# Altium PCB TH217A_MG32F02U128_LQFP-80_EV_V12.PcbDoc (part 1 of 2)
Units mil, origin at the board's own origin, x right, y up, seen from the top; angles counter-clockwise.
Board outline 4606.3 x 2637.8 mil, 2 copper layers (Top Layer, Bottom Layer); 131 components, 143 nets, 610 pads, 279 vias.
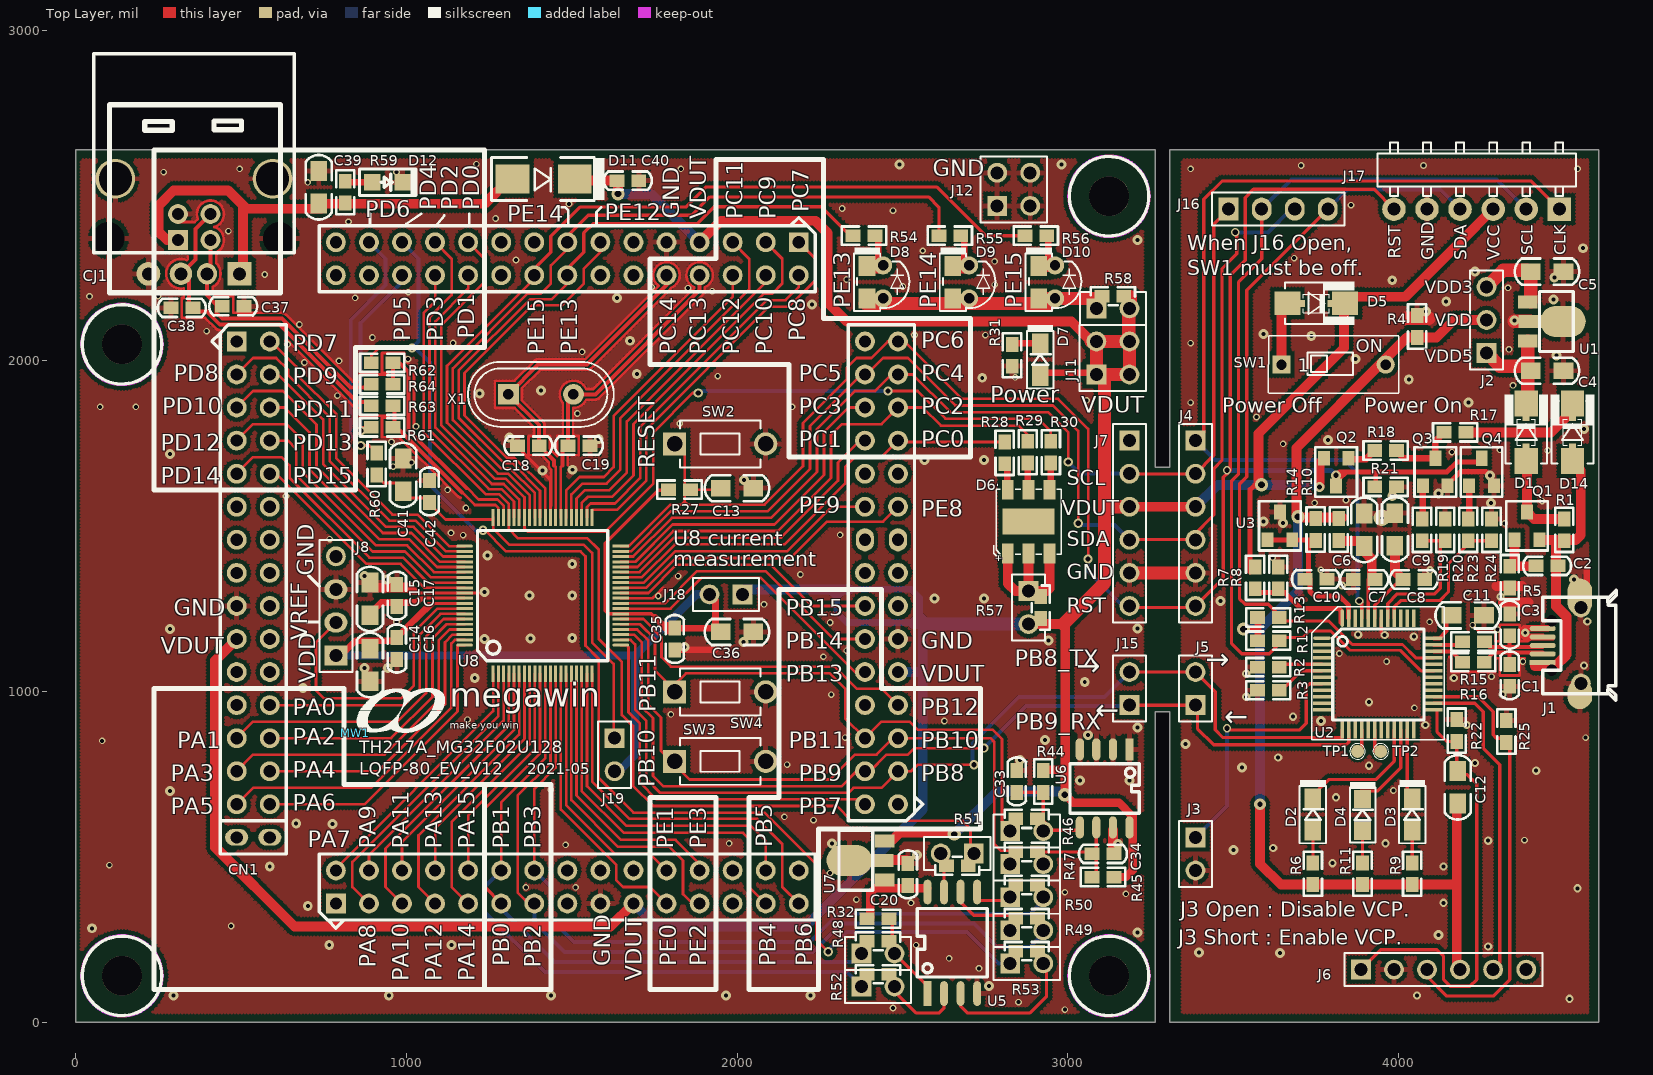
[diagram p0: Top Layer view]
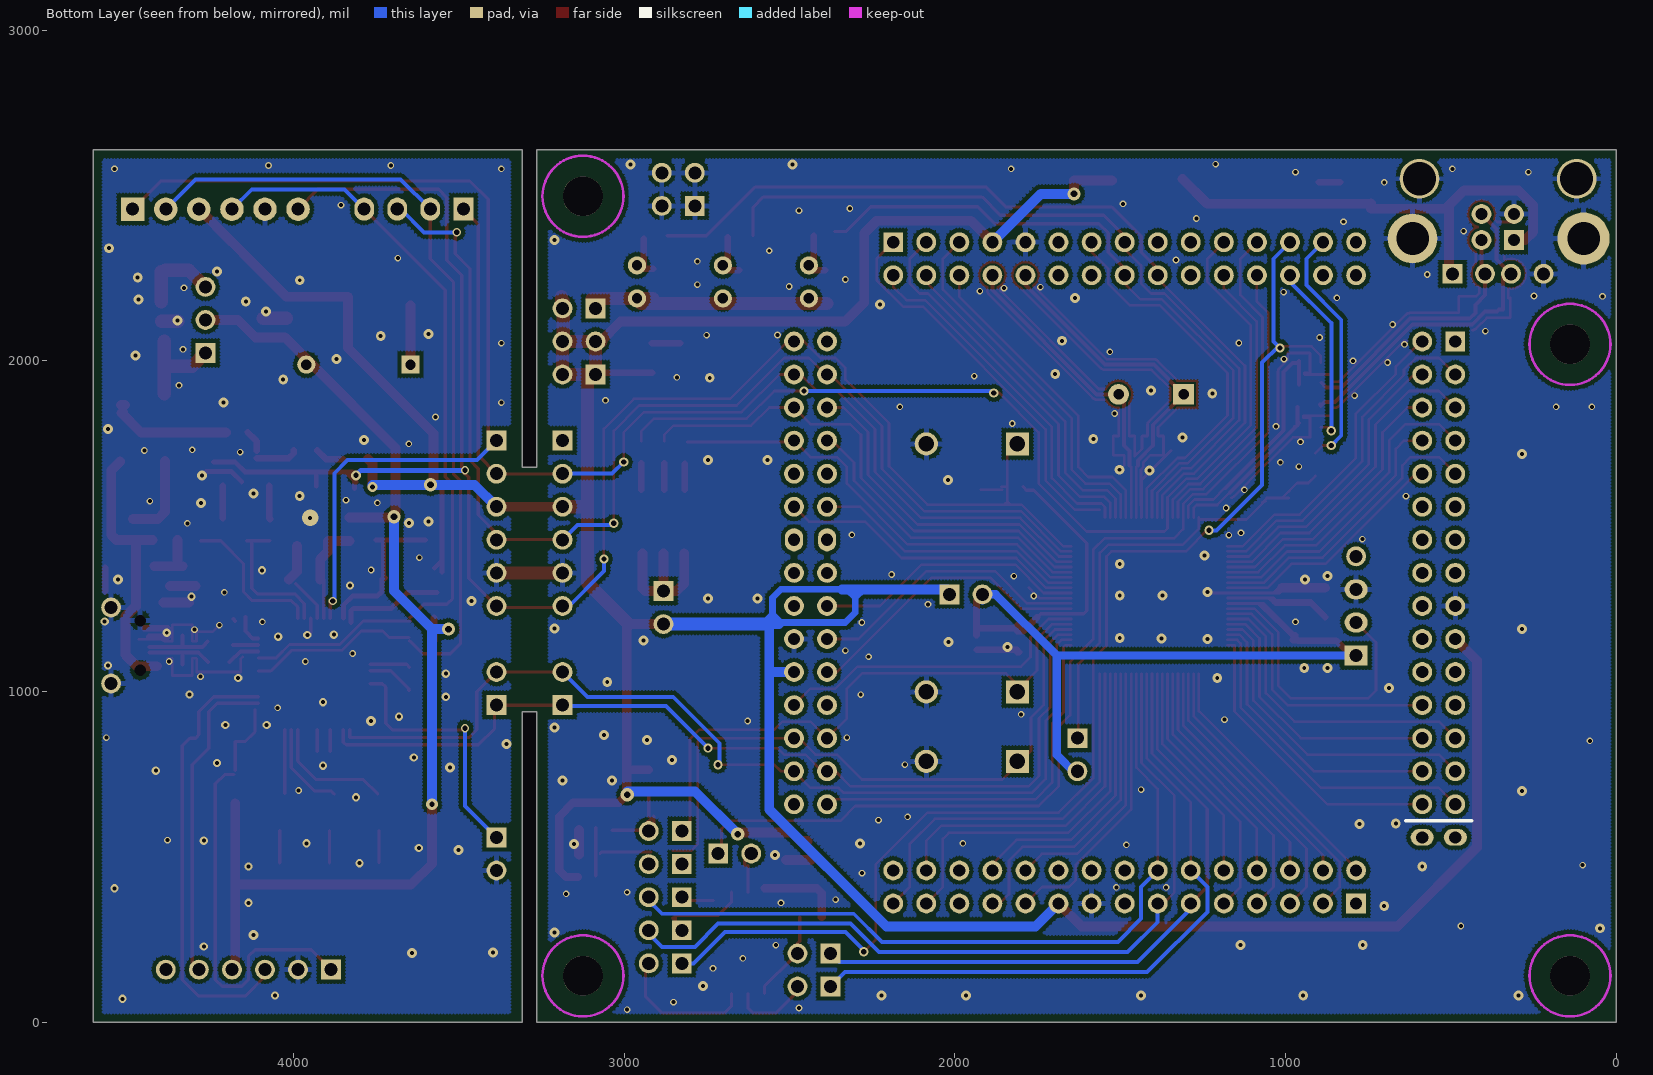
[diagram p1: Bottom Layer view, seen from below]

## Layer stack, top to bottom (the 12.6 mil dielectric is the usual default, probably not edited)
Top Layer: signal copper 1.4
Dielectric: dielectric 12.6, FR-4, Dk 4.8
Bottom Layer: signal copper 1.4

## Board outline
0,0 0,2637.8 3265.2,2637.8 3265.2,1678.74 3308.5,1678.74 3308.5,2637.8 4606.3,2637.8 4606.3,0 3308.5,0 3308.5,938.74 3265.2,938.74 3265.2,0

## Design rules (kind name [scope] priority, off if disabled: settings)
Clearance 12 [All] p1 off: gap=12
Clearance 7 [All] p2 off: gap=7
Clearance 6 [All] p3: gap=6
HoleSize 500-HoleSize [All] p1: absolutevalues=TRUE maxlimit=1500 minlimit=1 maxpercent=80.000 minpercent=20.000
PolygonConnect VIA [ISVIA] p1: connectstyle=Direct reliefconductorwidth=10 reliefentries=4 polygonreliefangle="90 Angle"
PolygonConnect "15 PolygonConnect" [All] p2: connectstyle=Relief reliefconductorwidth=15 reliefentries=4 polygonreliefangle="90 Angle"
RoomDefinition 2_MG32F02U128_V12 [InComponentClass('2_MG32F02U128_V12')] p1: confinementstyle=ConfineIn formatcopy=TRUE lockcomponents=FALSE outline -139,-81 4757,-81 4757,2954 -139,2954
RoomDefinition 1_MLink_V12 [InComponentClass('1_MLink_V12')] p2 off: confinementstyle=ConfineIn formatcopy=TRUE lockcomponents=FALSE outline -50,-126.26 4705.85,-126.26 4705.85,2998 -50,2998
RoutingVias [All] p1: holewidth=16 width=28 viastyle="Through Hole" minholewidth=16 minwidth=25 maxholewidth=28 maxwidth=50
ShortCircuit [All] p1 off: allowed=FALSE
SilkscreenOverComponentPads [All] p1: minsilkscreentomaskgap=10
SolderMaskExpansion [All] p1: expansion=4
UnRoutedNet [All] p1 off:
Width [All] p1: maxlimit=100 minlimit=6 preferedwidth=10
24 further rules are at their usual default settings.

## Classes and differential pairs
component class 2_MG32F02U128_V12: C13 C14 C15 C16 C17 C18 C19 C20 C33 C34 C35 C36 C37 C38 C39 C40 C41 C42 CJ1 CN1 D6 D7 D8 D9 D10 D11 D12 J7 J8 J11 J12 J15 J18 J19 R27 R28 R29 R30 R31 R32 R44 R45 R46 R47 R48 R49 R50 R51 R52 R53 R54 R55 R56 R57 R58 R59 R60 R61 R62 R63 R64 SW2 SW3 SW4 U5 U6 U7 U8 X1
component class 1_MLink_V12: C1 C2 C3 C4 C5 C6 C7 C8 C9 C10 C11 C12 D1 D2 D3 D4 D5 D14 J1 J2 J3 J4 J5 J6 J16 J17 MW1 Q1 Q2 Q3 Q4 R1 R2 R3 R4 R5 R6 R7 R8 R9 R10 R11 R12 R13 R14 R15 R16 R17 R18 R19 R20 R21 R22 R23 R24 R25 SW1 TP1 TP2 U1 U2 U3

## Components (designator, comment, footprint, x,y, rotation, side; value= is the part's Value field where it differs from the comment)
C1 "15pF" 0603C#1 4336.85,1048.74 r90 top
C2 "0.1uF" 0603C#2 4450,1380 r180 top
C3 "15pF" 0603C#1 4336.85,1201.74 r270 top
C4 "4.7uF" 0805C 4450,1970 r0 top
C5 "4.7uF" 0805C 4450,2270 r0 top
C6 "4.7uF" 0805C 3896.81,1488.74 r90 top
C7 "0.1uF" 0603C#2 3896.85,1338.74 r0 top
C8 "0.1uF" 0603C#2 4046.85,1338.74 r180 top
C9 "4.7uF" 0805C 3990,1490 r90 top
C10 "0.1uF" 0603C#2 3750.9,1339.69 r0 top
C11 "4.7uF" 0805C 4210,1230 r0 top
C12 "4.7uF" 0805C 4180,710 r90 top
C13 "4.7uF" 0805C 2000,1615 r180 top
C14 "4.7uF" 0805C 890,1080 r270 top
C15 "4.7uF" 0805C 890,1280 r90 top
C16 "0.1uF" 0603C#1 971.22,1130 r90 top
C17 "0.1uF" 0603C#1 971.22,1290 r270 top
C18 "NC" 0603C#1 1368.85,1743.74 r0 top
C19 "NC" 0603C#1 1521.85,1743.74 r180 top
C20 "1uF" 0603C#1 2516.85,446.74 r270 top
C33 "47pF" 0603C#1 2846.22,727.8 r270 top
C34 "47pF" 0603C#1 3106.85,508.74 r180 top
C35 "0.1uF" 0603C#1 1811.85,1158.74 r90 top
C36 "4.7uF" 0805C 2000,1180 r0 top
C37 "15pF" 0603C#2 476.22,2165 r0 top
C38 "15pF" 0603C#2 321.22,2160 r180 top
C39 "10uF/10V" 0805C 735,2525 r90 top
C40 "1uF" 0603C#2 1670,2545 r0 top
C41 "4.7uF" 0805C 990,1655 r90 top
C42 "0.1uF" 0603C#2 1070,1605 r90 top
CJ1 "CJ-USB-AB" CON_USB-AB 495.35,2263.31 r180 top locked
CN1 "QFP122-CKT" QFP122-P2.54-CKT 1486.85,1358.74 r0 top locked
D1 "1N5817" DIODE_SMA_SOD323 4386.81,1783.74 r90 top
D2 "Yellow" 0805D#1 3741.85,627.95 r90 top
D3 "Green" 0805D#1 4041.85,627.95 r90 top
D4 "Red" 0805D#2 3891.85,626.74 r90 top
D5 "1N5817" DIODE_SMA_SOD323 3751.81,2173.74 r0 top
D6 "GTG5050RGBC" LED6P_RGB_SMD_50X50 2881.85,1513.74 r90 top
D7 "Yellow" 0805D#1 2916.85,2003.74 r90 top
D8 "Red" LED38+0805 2441.85,2238.74 r90 top
D9 "Yellow" LED38+0805 2701.85,2238.74 r90 top
D10 "Green" LED38+0805 2961.85,2238.74 r90 top
D11 "B5817" D5817_SMD_1 1415,2550 r180 top
D12 "LED0805-Green" LED-0805 945,2540 r90 top
D14 "1N5817" DIODE_SMA_SOD323 4526.81,1783.74 r90 top
J1 "Micro USB" JACK_USB_SMD290X220P065 4436.85,1139.21 r180 top locked (schematic designator J8)
J2 "2&3 (0 ohm)" PS3P254 4266.85,2023.74 r90 top
J3 "VCP Option" PS2P254 3386.85,558.74 r270 top
J4 "OnBoard ICP/SWD Connector" PS6P254 3386.85,1758.74 r270 top locked
J5 "NC" PS2P254 3386.85,958.74 r90 top
J6 "CON6" PS6P254 3886.85,158.74 r0 top
J7 "CON6" PS6P254 3186.85,1758.74 r270 top locked
J8 "1&2 (0 ohm)" PS4P254#1 786.85,1108.74 r90 top
J11 "CONN SOCKET 2x2/SM" PS2X2P254 3086.85,1958.74 r0 top
J12 "CONN SOCKET 2x2/SM" PS2X2P254 2786.85,2468.74 r0 top
J15 "NC" PS2P254 3186.85,958.74 r90 top
J16 "When J16 Open, SW1 must be off." PS4P254#2 3486.85,2458.74 r0 top
J17 "Off Board ICP/SWD Connector" PS6P254_90 4486.85,2458.74 r180 top locked
J18 "JUMPER" PS2P254 2016.85,1293.74 r180 top
J19 "JUMPER" PS2P254 1629.85,858.74 r270 top
MW1 "MW-A4" MEGAWIN_3.4 844.85,873.73 r0 top
Q1 "IRLML6402" SOT23 4389.35,1500.71 r0 top
Q2 "2N3906" SOT23 3812.31,1663.74 r180 top
Q3 "3904" SOT23 4111.85,1663.74 r0 top
Q4 "3904" SOT23 4251.85,1663.74 r0 top
R1 "NC" 0603R#1 4501.85,1488.74 r270 top
R2 "0" 0603R#1 3606.85,1073.74 r0 top
R3 "NC" 0603R#1 3606.85,1003.74 r0 top
R4 "3.3K" 0603R#1 4056.85,2103.74 r270 top
R5 "1M" 0603R#1 4336.85,1345.74 r270 top
R6 "1K" 0603R#1 3741.85,448.74 r270 top
R7 "30K" 0603R#1 3566.85,1343.74 r90 top
R8 "10K" 0603R#1 3636.85,1343.74 r270 top
R9 "1K" 0603R#1 4041.85,448.74 r270 top
R10 "10" 0603R#1 3820,1490 r90 top
R11 "1K" 0603R#1 3891.85,448.74 r270 top
R12 "1.5K" 0603R#1 3606.85,1153.74 r180 top
R13 "1.5K" 0603R#1 3606.85,1223.74 r180 top
R14 "1K" 0603R#1 3750,1490 r270 top
R15 "30" 0603R#1 4227.69,1151.05 r180 top
R16 "30" 0603R#1 4226.85,1088.74 r180 top
R17 "4.7K" 0603R#1 4171.81,1783.74 r0 top
R18 "1K" 0603R#1 3961.85,1728.74 r0 top
R19 "4.7K" 0603R#1 4071.85,1488.74 r270 top
R20 "10K" 0603R#1 4141.85,1488.74 r270 top
R21 "1M" 0603R#1 3961.85,1618.74 r180 top
R22 "47K" 0603R#1 4176.85,881.74 r90 top
R23 "4.7K" 0603R#1 4211.85,1488.74 r270 top
R24 "10K" 0603R#1 4281.85,1488.74 r270 top
R25 "47K" 0603R#1 4326.85,878.74 r270 top
R27 "47K" 0603R#1 1826.22,1610.64 r180 top
R28 "510" 0603R#1 2809.41,1721.74 r90 top
R29 "510" 0603R#1 2879.41,1723.74 r90 top
R30 "3K" 0603R#1 2949.41,1723.74 r90 top
R31 "1K" 0603R#1 2831.85,2016.74 r270 top
R32 "47K" 0603R#1 2426.22,312.8 r0 top
R44 "10K" 0603R#1 2926.22,727.8 r90 top
R45 "10K" 0603R#1 3106.85,438.74 r0 top
R46 "NC" PS2p254+0603 2826.22,577.8 r0 top
R47 "NC" PS2p254+0603 2826.22,477.8 r0 top
R48 "NC" PS2p254+0603 2376.22,207.8 r0 top
R49 "NC" PS2p254+0603 2826.22,277.8 r0 top
R50 "NC" PS2p254+0603 2826.22,377.8 r0 top
R51 "NC" PS2p254+0603 2716.22,510 r180 top
R52 "NC" PS2p254+0603 2376.22,107.8 r0 top
R53 "NC" PS2p254+0603 2826.22,177.8 r0 top
R54 "510" 0603R#1 2383.85,2378.74 r180 top
R55 "510" 0603R#1 2643.85,2378.74 r180 top
R56 "510" 0603R#1 2903.85,2378.74 r180 top
R57 "0" PS2p254+0603 2881.85,1303.74 r270 top
R58 "0" PS2p254+0603 3086.85,2158.74 r0 top
R59 "3K" 0603R#2 815,2510 r90 top
R60 "0" 0603R#2 910,1688 r90 top
R61 "0" 0603R#2 926.85,1798.74 r180 top
R62 "0" 0603R#2 926.85,1993.74 r180 top
R63 "0" 0603R#2 926.85,1863.74 r180 top
R64 "0" 0603R#2 926.85,1928.74 r180 top
SW1 "SW KEY-SPST" DIP2_SW 3646.89,1988.74 r0 top
SW2 "SW TACT-SPST" SW_T_2P 1949.06,1748.74 r0 top
SW3 "SW TACT-SPST" SW_T_2P 1949.06,788.74 r0 top
SW4 "SW TACT-SPST" SW_T_2P 1949.06,998.74 r0 top
TP1 "T POINT A" PIN1_1H0 3876.85,818.74 r270 top
TP2 "T POINT A" PIN1_1H0 3946.85,818.74 r270 top
U1 "AIC1734-33(SOT-89)" SOT89 4391.81,2119.06 r270 top
U2 "MG84FG516_LQFP48" LQFP48_7X7_050 3938.32,1053.13 r270 top locked
U3 "TL431A" SOT23 3641.81,1500.71 r0 top
U5 "MX25LXX-SOP" SO8_208P127 2651.22,240 r0 top
U6 "24C16-SOP" SO8_150P127 3186.85,824.96 r270 top
U7 "AIC1734-33(SOT-89)" SOT89 2446.22,489.06 r90 top
U8 "MG32F02U128_LQFP80" QFP80-P0.4-Z12X12 1412.24,1289.96 r0 top locked
X1 "NC" X49U 1406.85,1898.74 r0 top

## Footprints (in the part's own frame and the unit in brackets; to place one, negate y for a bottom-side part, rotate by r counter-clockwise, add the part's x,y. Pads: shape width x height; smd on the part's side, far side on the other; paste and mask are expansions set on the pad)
0603C#1 [mil]
  rect 45x38 smd: 1(33,0) 2(-33,0)
  silkscreen extent -72,-28 72,28
0603C#2 [mil]
  rect 45x38 smd: 1(-33,0) 2(33,0)
  silkscreen extent -72,-28 72,28
0603R#1 [mil]
  rect 45x38 smd: 1(33,0) 2(-33,0)
  silkscreen extent -67,-28 67,28
0603R#2 [mil]
  rect 45x38 smd: 1(-33,0) 2(33,0)
  silkscreen extent -67,-28 67,28
0805C [mil]
  rect 60x50 smd: 1(-49.21,0) 2(49.21,0)
  silkscreen extent -97,-39 97,39
0805D#1 [mil]
  rect 60x50 smd: 1(-49.21,0) 2(49.21,0)
  silkscreen extent -87,-40 105,40
0805D#2 [mil]
  rect 55.12x51.18 smd: 1(-48,0) 2(48,0)
  silkscreen extent -84,-39 100,38
CON_USB-AB [mm]
  rect 1.824x1.824 / inner round 1.524 / far side rect 1.524x1.524 hole 1: 1(0,0)
  oval 1.524x1.651 / inner round 1.524 / far side round 1.524 hole 1: 2(2.5,0)
  round 1.724 / inner round 1.524 / far side round 1.524 hole 1: 3(4.5,0)
  round 1.824 / inner round 1.524 / far side round 1.524 hole 1: 4(7,0)
  round 1.524 / inner round 1.524 / far side round 3.81 hole 2.5: 5(-3.07,-2.71)
  round 1.524 / inner round 1.524 / far side round 4.013 hole 2.5: 6(10.07,-2.71)
  rect 1.524x1.524 hole 0.94: 7(4.73,-2.59)
  round 1.524 hole 0.94: 8(2.23,-2.59) 9(2.23,-4.59) 10(4.73,-4.59)
  round 3.048 hole 2.54: 11(-2.54,-7.3) 12(9.54,-7.3)
  silkscreen extent -4.2,-16.91 11.2,1.46
D5817_SMD_1 [mm]
  rect 2.6x2.2 smd: 1(2.39,0) 2(-2.39,0)
  silkscreen extent -4.67,-1.65 4,1.65
DIODE_SMA_SOD323 [mm]
  rect 2x1.8 smd: 1(-2.2,0) 2(2.2,0)
  rect 0.95x0.54 smd: 1(-1.35,0) 2(1.35,0)
  silkscreen extent -2.4,-1.68 2.92,1.68
DIP2_SW [mm]
  rect 1.4x1.4 hole 0.8: 1(0,0)
  round 1.4 hole 0.8: 2(8,0)
  silkscreen extent -1.02,-2.2 9.02,2.2
JACK_USB_SMD290X220P065 [mm]
  rect 1.9x1.8 on Mech2: 0(-2.85,-1.15) 0(-2.85,1.15)
  round 0.8 hole 0.9 unplated: 1(-0.7,1.9) 5(-0.7,-1.9)
  rect 2x0.4 smd: 1(0,1.3)
  oval 2x0.4 smd: 2(0,0.65) 3(0,0) 4(0,-0.65) 5(0,-1.3)
  round 1.524 hole 1: 5(-2.931,2.921) 6(-2.931,-2.921)
  oval 1.9x2.3 smd: 5(-2.85,3.75)
  oval 1.9x2.794 smd: 6(-2.85,-3.75)
  silkscreen extent -5.65,-4.25 -0.01,4.2
LED6P_RGB_SMD_50X50 [mm]
  rect 2x4 smd: 0(0,0)
  rect 1.5x0.9 smd: 1(-2.45,1.6) 2(2.45,1.6) 3(-2.45,0) 4(2.45,0) 5(-2.45,-1.6) 6(2.45,-1.6)
  silkscreen extent -2.63,-2.5 2.5,2.69
LED38+0805 [mm]
  round 1.4 hole 0.8: 1(-1.27,0) 2(1.27,0)
  rect 1.524x1.27 smd: 1(-1.267,1.237) 2(1.233,1.237)
  silkscreen extent -2.23,-2.02 2.64,2.25
LED-0805 [mil]
  rect 50x50 smd: 1(0,48) 2(0,-44)
  silkscreen extent -40,-83 40,87
LQFP48_7X7_050 [mm]
  oval 0.254x1.35 smd: 1(-2.75,-4.292)
  rect 0.254x1.35 smd: 2(-2.25,-4.292) 3(-1.75,-4.292) 4(-1.25,-4.292) 5(-0.75,-4.292) 6(-0.25,-4.292) 7(0.25,-4.292) 8(0.75,-4.292) 9(1.25,-4.292) 10(1.75,-4.292) 11(2.25,-4.292) 12(2.75,-4.292) 25(2.763,4.292) 26(2.263,4.292) 27(1.763,4.292) 28(1.263,4.292) 29(0.763,4.292) 30(0.263,4.292) 31(-0.237,4.292) 32(-0.737,4.292) 33(-1.237,4.292) 34(-1.737,4.292) 35(-2.237,4.292) 36(-2.737,4.292)
  rect 1.35x0.254 smd: 13(4.286,-2.744) 14(4.286,-2.244) 15(4.286,-1.744) 16(4.286,-1.244) 17(4.286,-0.744) 18(4.286,-0.244) 19(4.286,0.256) 20(4.286,0.756) 21(4.286,1.256) 22(4.286,1.756) 23(4.286,2.256) 24(4.286,2.756) 37(-4.286,2.756) 38(-4.286,2.256) 39(-4.286,1.756) 40(-4.286,1.256) 41(-4.286,0.756) 42(-4.286,0.256) 43(-4.286,-0.244) 44(-4.286,-0.744) 45(-4.286,-1.244) 46(-4.286,-1.744) 47(-4.286,-2.244)
  oval 1.35x0.254 smd: 48(-4.286,-2.744)
  silkscreen extent -5.15,-5.09 5.05,5.11
MEGAWIN_3.4 [mil]
  silkscreen extent 5,3 272,136
PIN1_1H0 [mm]
  round 1 smd: 1(0,0)
  silkscreen extent -0.6,-0.6 0.6,0.6
PS2P254 [mil]
  rect 60x60 hole 39.37: 1(0,0)
  round 60 hole 39.37: 2(100,0)
  silkscreen extent -50,-50 150,50
PS2p254+0603 [mil]
  rect 60x60 hole 39.37: 1(0,0)
  rect 45x38 smd: 1(17,36.85) 2(83,36.85)
  round 60 hole 39.37: 2(100,0)
  silkscreen extent -50,-50 150,64
PS2X2P254 [mil]
  rect 60x60 hole 39.37: 1(0,0)
  round 60 hole 39.37: 2(0,100) 3(100,0) 4(100,100)
  silkscreen extent -50,-50 150,150
PS3P254 [mil]
  rect 60x60 hole 39.37: 1(0,0)
  round 60 hole 39.37: 2(100,0) 3(200,0)
  silkscreen extent -50,-50 250,50
PS4P254#1 [mil]
  rect 60x70 hole 39.37: 1(0,0)
  oval 60x70 hole 39.37: 2(100,0) 3(200,0)
  round 60 hole 39.37: 4(300,0)
  silkscreen extent -50,-50 350,50
PS4P254#2 [mil]
  rect 60x70 hole 39.37: 1(0,0)
  oval 60x70 hole 39.37: 2(100,0) 3(200,0) 4(300,0)
  silkscreen extent -50,-50 350,50
PS6P254 [mil]
  rect 60x60 hole 39.37: 1(0,0)
  round 60 hole 39.37: 2(100,0) 3(200,0) 4(300,0) 5(400,0) 6(500,0)
  silkscreen extent -50,-50 550,50
PS6P254_90 [mm]
  rect 1.8x1.8 hole 1: 1(0,0)
  round 1.8 hole 1: 2(2.54,0) 3(5.08,0) 4(7.62,0) 5(10.16,0) 6(12.7,0)
  silkscreen extent -1.27,-5.11 13.97,-1
QFP80-P0.4-Z12X12 [mm]
  rect 0.229x1.27 smd: 1(-3.8,-6) 2(-3.4,-6) 3(-3,-6) 4(-2.6,-6) 5(-2.2,-6) 6(-1.8,-6) 7(-1.4,-6) 8(-1,-6) 9(-0.6,-6) 10(-0.2,-6) 11(0.2,-6) 12(0.6,-6) 13(1,-6) 14(1.4,-6) 15(1.8,-6) 16(2.2,-6) 17(2.6,-6) 18(3,-6) 19(3.4,-6) 20(3.8,-6) 41(3.8,6) 42(3.4,6) 43(3,6) 44(2.6,6) 45(2.2,6) 46(1.8,6) 47(1.4,6) 48(1,6) 49(0.6,6) 50(0.2,6) 51(-0.2,6) 52(-0.6,6) 53(-1,6) 54(-1.4,6) 55(-1.8,6) 56(-2.2,6) 57(-2.6,6) 58(-3,6) 59(-3.4,6) 60(-3.8,6)
  oval 1.27x0.229 smd: 21(6,-3.8) 61(-6,3.8) 80(-6,-3.8)
  rect 1.27x0.229 smd: 22(6,-3.4) 23(6,-3) 24(6,-2.6) 25(6,-2.2) 26(6,-1.8) 27(6,-1.4) 28(6,-1) 29(6,-0.6) 30(6,-0.2) 31(6,0.2) 32(6,0.6) 33(6,1) 34(6,1.4) 35(6,1.8) 36(6,2.2) 37(6,2.6) 38(6,3) 39(6,3.4) 40(6,3.8) 62(-6,3.4) 63(-6,3) 64(-6,2.6) 65(-6,2.2) 66(-6,1.8) 67(-6,1.4) 68(-6,1) 69(-6,0.6) 70(-6,0.2) 71(-6,-0.2) 72(-6,-0.6) 73(-6,-1) 74(-6,-1.4) 75(-6,-1.8) 76(-6,-2.2) 77(-6,-2.6) 78(-6,-3) 79(-6,-3.4)
  silkscreen extent -5,-5 5,5
QFP122-P2.54-CKT [mil]
  rect 60x60 hole 37: 1(-700,-1000) 61(700,1000) 91(-1000,700)
  round 60 hole 37: 2(-700,-900) 3(-600,-1000) 4(-600,-900) 5(-500,-1000) 6(-500,-900) 7(-400,-1000) 8(-400,-900) 9(-300,-1000) 10(-300,-900) 11(-200,-1000) 12(-200,-900) 13(-100,-1000) 14(-100,-900) 15(0,-1000) 16(0,-900) 17(100,-1000) 18(100,-900) 19(200,-1000) 20(200,-900) 21(300,-1000) 22(300,-900) 23(400,-1000) 24(400,-900) 25(500,-1000) 26(500,-900) 27(600,-1000) 28(600,-900) 29(700,-1000) 30(700,-900) 31(1000,-700) 32(900,-700) 33(1000,-600) 34(900,-600) 35(1000,-500) 36(900,-500) 37(1000,-400) 38(900,-400) 39(1000,-300) 40(900,-300) 41(1000,-200) 42(900,-200) 43(1000,-100) 44(900,-100) 45(1000,0) 46(900,0) 49(1000,200) 50(900,200) 51(1000,300) 52(900,300) 53(1000,400) 54(900,400) 55(1000,500) 56(900,500) 57(1000,600) 58(900,600) 59(1000,700) 60(900,700) 62(700,900) 63(600,1000) 64(600,900) 65(500,1000) 66(500,900) 67(400,1000) 68(400,900) 69(300,1000) 70(300,900) 71(200,1000) 72(200,900) 73(100,1000) 74(100,900) 75(0,1000) 76(0,900) 77(-100,1000) 78(-100,900) 79(-200,1000) 80(-200,900) 81(-300,1000) 82(-300,900) 83(-400,1000) 84(-400,900) 85(-500,1000) 86(-500,900) 87(-600,1000) 88(-600,900) 89(-700,1000) 90(-700,900) 92(-900,700) 93(-1000,600) 94(-900,600) 95(-1000,500) 96(-900,500) 97(-1000,400) 98(-900,400) 99(-1000,300) 100(-900,300) 101(-1000,200) 102(-900,200) 103(-1000,100) 104(-900,100) 105(-1000,0) 106(-900,0) 107(-1000,-100) 108(-900,-100) 109(-1000,-200) 110(-900,-200) 111(-1000,-300) 112(-900,-300) 113(-1000,-400) 114(-900,-400) 115(-1000,-500) 116(-900,-500) 117(-1000,-600) 118(-900,-600) 119(-1000,-700) 120(-900,-700)
  oval 55x70 hole 37: 47(1000,100) 48(900,100)
  oval 70x50 hole 37: 121(-1000,-800) 122(-900,-800)
  silkscreen extent -1075,-1075 1075,1075
SO8_150P127 [mil]
  rect 67x25 smd: 1(0,0)
  oval 67x25 smd: 2(0,-50) 3(0,-100) 4(0,-150) 5(236.22,-150) 6(236.22,-100) 7(236.22,-50) 8(236.22,0)
  silkscreen extent 43,-180 193,30
SO8_208P127 [mm]
  rect 0.6x1.9 smd: 1(-1.905,-3.9)
  oval 0.6x1.9 smd: 2(-0.635,-3.9) 3(0.635,-3.9) 4(1.905,-3.9) 5(1.905,3.9) 6(0.635,3.9) 7(-0.635,3.9) 8(-1.905,3.9)
  silkscreen extent -2.69,-2.63 2.69,2.63
SOT23 [mil]
  rect 36x43.31 smd: 1(-37.5,-41.97) 2(37.5,-41.97)
  rect 36x46.06 smd: 3(0.5,41.97)
  silkscreen extent -63,-74 63,75
SOT89 [mm]
  rect 1.016x1.5 smd: 1(-1.5,0) 3(1.5,0)
  oval 2.4x3.5 smd: 2(0,2.7)
  rect 1.016x2.6 smd: 2(0,0.6)
  silkscreen extent -2.3,0.9 2.3,3.5
SW_T_2P [mil]
  rect 70x70 hole 47.24: 1(-137.79,0)
  round 70 hole 47.24: 2(137.8,0)
  silkscreen extent -122,-71 122,71
X49U [mm]
  rect 1.6x1.6 hole 0.8: 1(-2.5,0)
  round 1.6 hole 0.8: 2(2.5,0)
  silkscreen extent -5.6,-2.5 5.6,2.5

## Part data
C1 C3 C7 C12 C13 C14 C15 C16 C17 C35 C36 C42: library part "CAP NP_Dup1"
C2 C8 C10: library part "CAP NP"
C4 C5: library part "C NP"
C6 C9 C11 C41: library part CAP
C18 C19: library part "C NP_Dup1"
C20 C33 C34 C37 C38 C40: library part CAP-NP
C39: library part CAP-POL
CN1: "CN1"
D1 D5 D14: library part "DIODE SCHOTTKY"
D2 D3 D4: library part Led0_0
D6: library part LED_GTG5050RGBC
D7 D8 D9 D10: library part LED_Dup1
D11: library part DIODE-SCHOTTKY-2
D12: library part LED
J1 J7: library part CON6_Dup1
J2: library part CON3
J3 J5 J15: library part CON2
J4 J17: library part CON6
J8 J16: library part CON4
MW1: library part MW_A4_2
Q1: library part "MOSFET P GSD"
Q2: library part "PNP BEC"
Q3 Q4: library part "NPN BEC"
R1 R2 R3 R4 R27: library part R_Dup4
R5 R6 R7 R8 R9 R11 R12 R13 R17 R18 R19 R22 R23 R25: library part R_Dup2
R10 R14 R15 R16 R28 R29 R30 R31 R32 R46 R47 R48 R49 R50 R51 R52 R53 R54 R55 R56 R57 R58 R60 R61 R62 R63 R64: library part R_Dup5
R20 R21 R24: library part R_Dup1
R44 R45 R59: library part R
U1 U7: library part AIC1722-33
U3: library part TL431/CYL
U5: library part ICM-25LXX
U6: library part ICM-24CXX
U8: library part IC-MG32F02U128-LQFP80
X1: library part CRYSTAL

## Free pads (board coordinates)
  round 120 hole 120 unplated: 0(140,140) 0(140,2050) 0(3125.2,140) 0(3125.2,2497.8)

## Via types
v1: diameter 20, hole 12, Top Layer to Bottom Layer, tented both sides, 126 vias
v2: diameter 30, hole 12, Top Layer to Bottom Layer, tented both sides, 95 vias
v3: diameter 25, hole 12, Top Layer to Bottom Layer, tented both sides, 32 vias
v4: diameter 28, hole 16, Top Layer to Bottom Layer, tented both sides, 12 vias
v5: diameter 40, hole 20, Top Layer to Bottom Layer, tented both sides, 6 vias
v6: diameter 25, hole 16, Top Layer to Bottom Layer, tented both sides, 4 vias
v7: diameter 30, hole 16, Top Layer to Bottom Layer, tented both sides, 2 vias
v8: diameter 50, hole 12, Top Layer to Bottom Layer, tented both sides, 1 vias
v9: diameter 35, hole 16, Top Layer to Bottom Layer, tented both sides, 1 vias

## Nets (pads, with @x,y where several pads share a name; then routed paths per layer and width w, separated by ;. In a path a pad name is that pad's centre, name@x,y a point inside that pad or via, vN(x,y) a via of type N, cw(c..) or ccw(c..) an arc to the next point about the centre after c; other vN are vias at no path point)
2.495V: C10.1 R14.1 U2.47 U3.1 U3.2 | length 482.7
  Top Layer w15: U3.1@3601.81,1458.74 U3.1@3604.31,1458.74 U3.2@3679.31,1458.74 ; U3.2@3689.31,1458.74 3750,1458.74 R14.1@3751.81,1458.74 ; C10.1@3722.16,1343.94 C10.1@3733.07,1333.03 ; C10.1@3728.07,1339.69 3728.07,1456.77 ; C10.1@3733.07,1339.69 C10.1@3733.07,1333.03 ; U2.47@3849.99,1221.87 3849.99,1260.6 3821.85,1288.74 3746.85,1288.74 3733.07,1302.52 C10.1@3733.07,1333.03
+5V_USB: C39.1 CJ1.1 CJ1.7 D11.1 R59.1 | length 1499
  Top Layer w30: CJ1.7@319.13,2365.28 CJ1.7@309.13,2365.28 275.94,2365.28 251.22,2390 251.22,2470 296.22,2515 461.22,2515 505.35,2470.87 ; CJ1.1@505.35,2263.31 505.35,2470.87 ; C39.1@741.85,2460 735,2460 516.22,2460 505.35,2470.87 ; C39.1@741.85,2475.32 742.17,2475 815,2475 1236.85,2475 D11.1@1311.85,2550
CHIP_VDD: C14.1 C16.1 C35.1 C36.1 J8.1 J18.2 J19.2 R27.1 U8.27 U8.72 | length 3106.5
  Top Layer w8: 1054.25,1253.74 1066.85,1266.34
  Top Layer w9: 1061.85,1243.74 1084.45,1266.34 ; 1066.85,1266.34 1084.45,1266.34 ; U8.72@1176.02,1266.34 1084.45,1266.34
  Top Layer w10: 1751.85,1223.74 1740.75,1234.84 U8.27@1648.46,1234.84 1610.75,1234.84 1601.85,1243.74 1601.85,1448.74 1761.85,1608.74 1783.85,1608.74 1789.49,1614.38 R27.1@1793.85,1618.74
  Top Layer w20: J8.1@796.85,1103.74 846.85,1153.74 890,1153.74 961.85,1153.74 971.17,1163.06 C16.1@978.11,1170 ; C16.1@971.22,1155 977.54,1155 C16.1@978.38,1155.84 ; C16.1@971.22,1170 C16.1@978.11,1170 ; 1066.85,1258.74 C16.1@978.11,1170 ; 1751.85,1223.74 1793.85,1181.74 C35.1@1811.85,1181.74 ; 1776.22,1200 C35.1@1811.85,1200 ; C35.1@1811.85,1191.74 C36.1@1935,1191.74 ; J18.2@1916.85,1293.74 1935,1275.59 C36.1@1935,1191.74 ; C36.1@1935,1170 1935,1180 C36.1@1935,1191.74
  Bottom Layer w25: J8.1@786.85,1108.74 1692,1108.74 ; J19.2@1633,749 1636.3,752.3 1692,808 1692,1108.74 ; J18.2@1916.85,1293.74 1877,1293.74 1692,1108.74
  Bottom Layer w30: J18.2@1916.85,1278.74 J18.2@1916.85,1293.74
D+: C3.1 J1.3 R15.2 | length 211.2
  Top Layer w12: R15.2@4260.69,1151.05 4276.52,1135.21 J1.3@4436.85,1135.21 ; 4336.85,1140.21 C3.1@4336.85,1168.74
D-: C1.1 J1.2 R16.2 | length 219.3
  Top Layer w12: R16.2@4259.85,1088.74 4288.32,1117.21 J1.2@4436.85,1117.21 ; C1.1@4336.85,1081.74 4336.85,1112.21
DET_VDUT: R7.2 R8.1 U2.48 | length 317.8
  Top Layer w15: R7.2@3566.85,1298.74 3636.85,1298.74 3656.85,1298.74 3704.09,1251.51 3819.09,1251.51 3826.85,1243.74 3826.85,1221.87 U2.48@3826.85,1208.74
DUT_CLK: J4.1 J17.1 U2.45 | length 2898.3
  Top Layer w10: J4.1@3386.85,1758.74 3411.85,1783.74 3411.85,2488.74 3466.85,2543.74 4401.85,2543.74 J17.1@4486.85,2458.74 ; v6@3876.73,1273.74 3879.23,1271.24 3889.36,1261.11 ; U2.45@3889.36,1221.87 3889.36,1261.11 ; v6@3889.36,1273.74 3889.36,1261.11
  Bottom Layer w12: J4.1@3386.85,1758.74 3445.59,1700 3836.73,1700 3876.73,1660 3876.73,1568.74 ; v6@3876.73,1273.74 3876.73,1568.74 ; 3876.73,1606.93 3876.73,1568.74
  other v6: 3881.73,1273.74
FAIL: D4.2 U2.22 | length 278.6
  Top Layer w10: D4.2@3876.85,689.74 3885.85,698.74 3891.85,698.74 3936.85,698.74 4007.47,769.36 U2.22@4007.47,884.39
FLASH_CEN: R32.1 R48.2 U5.1 | length 275.7
  Top Layer w10: R32.1@2469.22,317.8 2469.22,312.8 2469.22,244.8 2491.22,222.8 2491.22,207.8 2491.22,192.8 2576.22,107.8 U5.1@2576.22,86.46
FLASH_D0: R50.1 U5.5 | length 94.3
  Top Layer w10: U5.5@2731.22,367.8 R50.1@2825.47,367.8
FLASH_D1: R52.2 U5.2 | length 261.8
  Top Layer w10: R52.2@2476.22,127.8 R52.2@2476.22,107.8 2476.22,92.8 2541.22,27.8 2611.22,27.8 2626.22,42.8 U5.2@2626.22,86.46
FLASH_D2: R53.2 U5.3 | length 427.7
  Top Layer w10: U5.3@2676.22,86.46 2676.22,47.8 2696.22,27.8 2886.22,27.8 2936.22,77.8 R53.2@2936.22,177.8
FLASH_D3: R51.2 U5.7 | length 132.7
  Top Layer w10: R51.2@2621.22,520 2623.72,517.5 2636.22,505 R51.2@2636.22,473.15 ; U5.7@2626.22,393.19 U5.7@2626.22,393.54 R51.2@2626.22,472.8
FLASH_SCK: R49.1 U5.6 | length 241.4
  Top Layer w10: U5.6@2676.22,393.54 2676.22,362.8 2716.22,322.8 2843.22,322.8 2845.07,322.8 2846.37,321.5 2846.37,314.65 2846.37,307.8 2848.22,309.65 R49.1@2853.22,314.65
GND_POWER: C1.2 C3.2 C4.2 C5.2 C6.2 C7.1 C8.1 C9.2 C10.2 C11.2 C13.1 C14.2 C15.2 C16.2 C17.2 C18.2 C19.2 C20.2 C33.2 C34.2 C35.2 C36.2 C37.2 C38.2 C39.2 C40.2 C41.2 C42.2 CJ1.4 CJ1.5 CJ1.6 CJ1.10 CJ1.11 CJ1.12 CN1.17 CN1.41 CN1.69 CN1.107 D12.2 J1.4 J1.5 J1.6 J3.2 J4.5 J6.2 J7.5 J8.3 J12.1 J12.2 J12.3 J12.4 J17.5 Q3.2 Q4.2 R2.2 R3.2 R4.2 R5.1 R8.2 R20.2 R21.2 R22.1 R24.2 R25.2 R31.1 SW2.2 SW3.2 SW4.2 U1.2 U2.42 U3.3 U5.4 U6.1 U6.2 U6.3 U6.4 U6.7 U7.2 U8.30 U8.49 U8.70 | length 9632.2
  Top Layer w8: CJ1.10@310,2420 359.5,2420 369.16,2429.65 cw(c407.56,2444.02) 448.56,2444.02 cw(c407.56,2444.02) 419,2404.65 cw(c407.56,2365.28) 448.56,2365.28 cw(c407.56,2365.28) 424.56,2327.97 424.56,2296.1 cw(c396.93,2265.81) 437.93,2265.81 437.93,2260.81 cw(c396.93,2260.81) 413.93,2223.5 413.93,2205.7 424.63,2195 476.72,2195 476.72,2145 509.22,2145 623.68,2145 ; 338.85,2316.5 338.85,2308.01 335.58,2304.74 ccw(c318.19,2263.31) 326.19,2219.09 326.19,2190 320.72,2190 320.72,2130 391.55,2130 423.55,2098 ; 633.84,2059.86 640.4,2059.86 642.32,2059.86 646.34,2055.84 699.2,2002.98 799.2,1902.98 839.18,1863 ; 635.7,2140.02 ccw(c623.68,2128) 623.68,2145 ; 926.35,1833.74 860.35,1833.74 860.35,1858 851.22,1858 ; 926.35,1958.74 860.35,1958.74 860.35,1937 838.72,1937 670.97,2104.75 635.72,2140 ccw(c623.68,2128) 623.68,2145 ; 927.35,1833.74 947.22,1833.74 947.22,1828.74 926.35,1828.74 926.35,1768.74 955,1768.74 977.98,1768.74 1016.26,1730.47 1089.36,1657.36 1130.86,1615.86 1156.47,1590.25 ccw(c1168.49,1602.27) 1164.18,1585.83 ; 927.35,1958.74 942.85,1958.74 942.85,1963.74 926.35,1963.74 926.35,2023.74 993.35,2023.74 993.35,2005 993.35,2003.21 998.28,1998.28 1018.22,1978.34 cw(c1006.22,1966.3) 1023.22,1966.3 ; 1018.24,1978.32 cw(c1006.22,1966.3) 1023.22,1966.3 ; v1@1023.22,1797.04 1023.22,1802 1023.22,1966.3 ; U8.49@1437.11,1526.18 1437.11,1561.18 ; 1437.61,1561.18 1437.61,1670.51 cw(c1446.61,1683.74) 1430.61,1683.74 1430.61,1692.35 1408.22,1714.74 1369.35,1714.74 1369.35,1772.74 1385.85,1772.74 1385.85,1798.69 1327.29,1857.24 1266.93,1857.24 1266.93,1940.24 1327.29,1940.24 1387.1,2000.04 ; 1456.36,1711.86 1434.35,1733.87 1434.35,1772.74 1417.85,1772.74 1417.85,1805.32 ; 1456.35,1714.74 1456.35,1772.74 1472.85,1772.74 1472.85,1872.85 cw(c1505.28,1898.74) 1543.56,1914.74 1565.22,1914.74 1861.12,2210.63 1870.85,2220.37 ; 1488.36,1683.74 1488.36,1714.74 1521.35,1714.74 1521.35,1772.74 1504.85,1772.74 1504.85,1840.64 1504.85,1857.25 ccw(c1505.28,1898.74) 1543.56,1882.74 1571.85,1882.74 ; 1558.16,1977.43 cw(c1546.85,1988.74) 1546.85,1972.74 ; 1583.16,1887.43 cw(c1571.85,1898.74) 1571.85,1882.74 ; U8.30@1648.46,1282.09 1745.2,1282.09 1756.85,1293.74 1776.85,1313.74 ; 1798.16,2217.43 ccw(c1786.85,2228.74) 1801.04,2221.34 ; 1870.85,2222.08 cw(c1886.85,2258.74) 1926.85,2258.74 cw(c1886.85,2258.74) 1902.85,2222.08 1902.85,2213.74 ; 1898.16,2202.43 ccw(c1886.85,2213.74) 1902.85,2213.74 ; 4154.02,1104.53 4160.35,1098.2 4160.35,1058.74 4226.35,1058.74 ; v1(4225,1200.64) 4244.6,1181.05 4294.19,1181.05 4294.19,1152.21 4306.85,1152.21 4306.85,1187.05 4306.85,1202.24 4366.85,1202.24 4366.85,1152.21 4391.67,1152.21 cw(c4405.35,1139.21) 4405.35,1158.09 4436.85,1158.09 J1.4@4468.35,1158.09 ; 4227.35,1058.74 4281.75,1058.74 4293.35,1058.74 4293.35,1098.2 ; 4295.36,1100.21 4306.85,1100.21 4306.85,1048.24 4366.85,1048.24 4366.85,1090.64 4366.85,1100.21 4376.85,1100.21 4382.49,1100.21 ; 423.55,2098 ccw(c435.59,2110) 435.59,2093 cw(c435.59,2110) 423.57,2097.98 ; 839.2,1862.98 ccw(c851.22,1875) 851.22,1858 ; 839.18,1863 ccw(c851.22,1875) 851.22,1858 ; 1387.11,2000.05 cw(c1398.43,1988.74) 1398.43,2004.74 ; 1387.1,2000.04 cw(c1398.43,1988.74) 1398.43,2004.74 ; 1398.43,2004.74 1540.22,2004.74 1750.12,2214.63 1762.49,2227.01 cw(c1786.85,2258.74) 1826.85,2258.74 cw(c1786.85,2258.74) 1801.04,2221.34 ; 1413.16,1816.63 cw(c1401.85,1805.32) 1417.85,1805.32 ; 1413.15,1816.64 cw(c1401.85,1805.32) 1417.85,1805.32 ; 1413.15,1816.64 1349.92,1879.87 1349.92,1917.61 1405.05,1972.74 1546.85,1972.74 ; 1546.85,1972.74 ccw(c1546.85,1988.74) 1558.18,1977.44 1798.15,2217.41 ccw(c1786.85,2228.74) 1801.04,2221.34 ; 1571.85,1882.74 ccw(c1571.85,1898.74) 1583.18,1887.44 1898.15,2202.41 ccw(c1886.85,2213.74) 1902.85,2213.74
  Top Layer w9: C15.2@901.22,1323 C15.2@910.48,1313.74 ; 1007.22,1307.8 1017.18,1297.83 1026.22,1297.83 ; 1010.31,1313.74 1026.22,1297.83 ; 1021.85,1313.74 1037.76,1297.83 ; U8.70@1176.02,1297.84 1037.76,1297.83 ; 1026.22,1297.83 1037.76,1297.83
  Top Layer w10: U8.70@1176.02,1297.84 v2@1231.85,1297.83 ; C18.2@1346.85,1728.74 1409.35,1666.24 1435.87,1639.72 U8.49@1435.87,1526.18 ; 3948.41,1177.75 U2.42@3948.41,1221.87
  Top Layer w15: Q3.2@4157.1,1634.03 4188.05,1664.98 4265.51,1664.98 v2(4276.75,1653.74)
  Top Layer w20: C35.2@1806.22,1118.9 C35.2@1811.85,1118.9 ; C35.2@1811.85,1125.74 1841.22,1125.74 1934.26,1125.74 ; v3@4380.73,1166.05 4384.02,1166.05 J1.4@4436.85,1166.05 ; 4380.73,1191.64 4384.02,1191.64 4436.85,1191.64 J1.5@4451.85,1191.64 ; J1.6@4570.5,1302.62 4570.5,1373.74
  Top Layer w30: C15.2@880.48,1313.74 890,1313.74 910.48,1313.74 941.85,1313.74 971.22,1313.74 1010.31,1313.74 1011.85,1313.74 ; U7.2@2436.22,490 C20.2@2511.22,490 ; C34.2@3136.85,506.84 3136.85,508.74 3136.85,538.74 U6.7@3136.85,580.64 ; 4296.85,1318.74 4336.85,1318.74 4373.85,1318.74 ; 4316.85,1268.74 4336.85,1268.74 4393.85,1268.74
  Top Layer w40: J7.5@3186.85,1358.74 J4.5@3386.85,1358.74 ; 4021.75,2128.74 4056.85,2128.74 4084.41,2128.74 4092.85,2128.74 ; v2@4349.94,2120 4351.75,2120 U1.2@4400,2120
  other v1: 2991.75,37.8 2471.75,42.8 2851.22,60.64 2731.75,162.8 2641.75,192.8 2541.75,232.8 470,290.64 2526.22,360.64 2361.22,370.64 3176.22,387.8 2991.75,392.8 1361.22,407.8 1511.75,407.8 2281.22,450.64 101.75,475 1481.75,536 1976,540.64 4381.85,550.64 2231.22,610.64 2143,620.64 3985,700.64 1436.85,703 2151.75,778.74 80,850.64 2326.85,860.64 4566.85,860.64 2626.85,910.64 1185,915 1800,930.64 4048.85,950.64 2285,990.64 4281.75,1045 3964.85,1090.64 4376.85,1090.64 2261.22,1105 3821.75,1114.74 2331.75,1123.74 4300.19,1187.05 2281.75,1208.74 970,1210.64 4095,1210.64 2081.75,1263.74 1761.85,1288.74 4210,1300 1821.85,1348.74 2191.75,1353.74 3765.9,1367.25 3620,1405 768,1460.64 1171.75,1472.8 2311.75,1473.74 1135,1480 4321.75,1508.74 1180,1555 3746.81,1570.64 4435,1575.82 3841.75,1578.71 636,1590.64 1125,1610 960,1680 1016,1693 4161.75,1723.74 4451.75,1728.74 4306.81,1730.64 3651.75,1748.74 955,1755 1029,1802 1826.85,1810.64 3571.22,1830 1517,1840.64 74,1860.64 181.75,1861 2166.85,1860.64 3371.75,1873.74 3056.85,1880.64 791.22,1895 4346.85,1925.64 2841.22,1949.81 1941.75,1953.74 691.22,1995 796.22,2000 1005,2005 1531.75,2027 4335,2035 640.4,2049.89 1141.75,2054 3371.75,2053.74 897,2070.64 2536.85,2078 2751.22,2077.8 396.22,2090 676.22,2110 845,2190.64 41.75,2195 248.72,2196 1006.22,2207.8 1925,2210.64 1851.75,2220 4331.81,2220.64 1741.75,2223 2501.75,2225 2779,2230.64 2331.75,2246 571.75,2261 2779,2300.64 1331.75,2305 3685,2310.64 2561.75,2333 461.75,2392 825,2420.64 1270,2430.64 2471.75,2454 2318,2460.64 3856.85,2470.64 1491.75,2475 701.75,2540 266,2570.64 970,2570.64 496,2580.64 1830,2580.64 3371.85,2580.64 4541.85,2580.64 3706.22,2590.64 4076.22,2590.64 1211.75,2595
  other v2: 295.63,80.64 946.85,80.64 1436.85,80.64 1966.85,80.64 2221.85,80.64 2761.75,108.74 3641.75,208.74 3396.85,210.64 766.75,233.74 1136.75,233.74 4121.75,263.74 3211.85,270.64 48.63,283.84 701.85,350.64 586.85,470.64 2544.54,505.9 3501.85,520.64 3151.75,538.74 2286.85,540.64 776.85,598.74 666.85,600.64 284.85,698.84 3036.85,730.64 3186.85,730.64 3526.85,770.64 2856.22,792.8 3356.85,840.64 2931.22,852.8 3061.75,868.74 3211.85,890.64 3766.85,910.64 686.85,1010.64 3051.75,1028.74 1206.85,1040.64 873.66,1070.84 943.66,1070.84 1841.22,1135 2020,1150 2941.75,1153.74 1236.85,1158.74 1376,1160.64 1501.75,1162 284.85,1188.84 3211.85,1190.64 3461.75,1273.74 2596.85,1280.64 2746.85,1280.64 1501.75,1290 1372,1290.64 1236.85,1300.64 941.85,1338.74 4531.75,1338.74 873.66,1349.16 1501.75,1386 1245,1410.64 3651.75,1510 3591.75,1513.74 4280,1570 3981.81,1591.18 4121.75,1598.74 2021.75,1640 1411.85,1668.74 1501.85,1670.64 2566.85,1700.64 2746.85,1700.64 284.85,1718.84 3786.81,1760.64 1581.75,1763.74 1311.75,1768.74 4561.75,1793.74 4211.81,1873.74 1221.85,1900.64 1406.85,1910.64 4031.75,1943.74 2741.75,1948.74 1696.85,1960.64 3870,2005 4478.85,2015.64 1676.85,2060.64 3736.85,2075.35 3591.85,2080.64 4351.75,2121.74 4084.41,2148.74 2226.85,2170.64 4145,2180 4469.85,2185.64 1636.85,2190.64 3981.75,2243.74 4471.75,2251.74 4231.75,2269.74 4558.85,2340.64 3211.75,2365 2491.75,2593.74 2981.75,2593.74
  other v3: 4517.85,70.64 4056.85,80.64 4271.75,228.74 4136.85,360.64 4541.75,404.74 4136.85,470.64 3801.22,480.64 3621.75,526.74 3961.22,540.64 4271.75,548.74 3811.75,680 4416.85,760.64 3911.75,775.74 4231.75,783.74 3636.85,800.64 4081.75,898.74 4206.85,898.74 3681.75,923.74 3911.75,967.74 3539.92,983.74 4314.85,990.64 4167.85,1040.64 3539.92,1053.74 4561.75,1078.74 4046.85,1165.74 3958.85,1170.74 3878.85,1171.74 4384.02,1177.6 4571.75,1211.45 4309.29,1286.74 3830,1320.64 4096.22,1366.3
  other v8: 3950.58,1525
I2C_SCL: C34.1 R45.2 R47.2 U6.6 | length 303
  Top Layer w10: R47.2@2919.22,514.65 3067.95,514.65 C34.1@3073.85,508.74 ; R45.2@3086.85,442.8 3086.85,508.74 U6.6@3086.85,588.74
I2C_SDA: C33.1 R44.2 R46.2 U6.5 | length 350.9
  Top Layer w10: C33.1@2846.22,694.8 R44.2@2926.22,694.8 ; R46.2@2911.22,577.8 2911.22,614.65 2911.22,622.8 2914.3,619.72 R46.2@2936.22,597.8 ; R46.2@2921.22,580 2926.22,580 U6.5@3036.22,580 ; R46.2@2926.22,621.65 R44.2@2926.22,694.8 ; R44.2@2926.22,697.24 R44.2@2926.22,694.8
ICP/SWD_SCL: J16.2 J17.2 R12.2 U2.31 | length 3098
  Top Layer w9: R12.2@3651.85,1163.74 3711.85,1163.74 3730.85,1182.74 3795.81,1182.74 3853.81,1124.74 4005.81,1124.74 4068.1,1062.45 ; 4068.12,1062.47 U2.31@4107.31,1062.47
  Top Layer w10: 3516.85,2228.74 3516.85,2078.74 ; J16.2@3586.85,2483.74 J16.2@3586.85,2458.74 3586.85,2308.74 3516.85,2238.74 3516.85,2078.74 ; R12.2@3649.85,1153.74 3644.85,1148.74 3609.85,1113.74 3526.85,1113.74 3495.6,1144.99 3495.6,1637.49 3516.85,1658.74 3516.85,2078.74
  Bottom Layer w12: J16.2@3586.85,2458.74 3676.85,2548.74 4296.85,2548.74 J17.2@4386.85,2458.74
ICP/SWD_SDA: J16.4 J17.4 R13.2 U2.33 | length 2398.9
  Top Layer w9: R13.2@3646.85,1213.74 3788.85,1213.74 3860.85,1141.74 4012.85,1141.74 4052.75,1101.84 U2.33@4107.31,1101.84
  Top Layer w10: R13.2@3649.85,1223.74 3646.85,1223.74 3643.35,1227.24 3606.85,1263.74 3536.85,1263.74 3519.6,1280.99 3519.6,1626.49 3541.85,1648.74 3541.85,2213.74 J16.4@3786.85,2458.74
  Bottom Layer w12: J16.4@3786.85,2458.74 3846.85,2518.74 4126.85,2518.74 J17.4@4186.85,2458.74
MG_DM: C37.1 CJ1.2 CJ1.8 R64.2 | length 786.3
  Top Layer w12: CJ1.2@396.93,2263.31 396.93,2198.66 426.22,2169.37 426.22,2165 426.22,2145 443.22,2128 623.68,2128 831.68,1920 878.11,1920 890.35,1932.24 R64.2@891.85,1933.74 ; CJ1.2@407.56,2273.94 CJ1.8@407.56,2365.28
MG_DP: C38.1 CJ1.3 CJ1.9 R63.2 | length 994.7
  Top Layer w12: CJ1.3@318.19,2263.31 361.85,2306.97 361.85,2398.31 CJ1.9@407.56,2444.02 ; CJ1.3@343.19,2258.31 343.19,2160 343.19,2155 354.22,2155 360.48,2148.74 396.85,2148.74 435.59,2110 616.22,2110 851.22,1875 882.59,1875 R63.2@893.85,1863.74 ; R63.2@893.85,1868 R63.2@896.22,1868
MG_PA0: CN1.114 U8.74 | length 801.3
  Top Layer w8: CN1.114@586.85,958.74 993.74,958.74 1040.85,1005.85 1040.85,1172.74 1102.95,1234.84 U8.74@1176.02,1234.84
MG_PA1: CN1.115 U8.75 | length 939.1
  Top Layer w8: CN1.115@486.85,858.74 536.85,908.74 973.74,908.74 1059.85,994.85 1059.85,1166.74 1112.2,1219.09 U8.75@1176.02,1219.1
MG_PA2: CN1.116 U8.76 | length 835.5
  Top Layer w8: CN1.116@586.85,858.74 953.74,858.74 1078.85,983.85 1078.85,1160.74 1121.46,1203.35 U8.76@1176.02,1203.35
MG_PA3: CN1.117 U8.77 | length 973.4
  Top Layer w8: CN1.117@486.85,758.74 536.85,808.74 933.74,808.74 1097.85,972.85 1097.85,1154.74 1130.71,1187.6 U8.77@1176.02,1187.6
MG_PA4: CN1.118 U8.78 | length 869.8
  Top Layer w8: CN1.118@586.85,758.74 913.74,758.74 1116.85,961.85 1116.85,1148.74 1139.96,1171.85 U8.78@1176.02,1171.85
MG_PA5: CN1.119 U8.79 | length 1009.2
  Top Layer w8: CN1.119@486.85,658.74 536.85,708.74 893.74,708.74 1135.85,950.85 1135.85,1145.45 1146.5,1156.1 U8.79@1176.02,1156.1
MG_PA6: CN1.120 U8.80 | length 906.1
  Top Layer w8: CN1.120@586.85,658.74 873.74,658.74 1154.85,939.85 1154.85,1140.35 U8.80@1176.02,1140.35
MG_PA7: CN1.2 U8.1 | length 792.1
  Top Layer w8: CN1.2@786.85,458.74 786.85,464.85 1262.64,940.64 U8.1@1262.64,1053.74
MG_PA8: CN1.3 U8.2 | length 898.6
  Top Layer w8: CN1.3@886.85,358.74 836.85,408.74 836.85,484.85 1278.39,926.39 U8.2@1278.39,1053.74
MG_PA9: CN1.4 U8.3 | length 763.7
  Top Layer w8: CN1.4@886.85,458.74 886.85,504.85 1294.13,912.13 U8.3@1294.13,1053.74
MG_PA10: CN1.5 U8.4 | length 870.2
  Top Layer w8: CN1.5@986.85,358.74 936.85,408.74 936.85,524.85 1309.88,897.88 U8.4@1309.88,1053.74
MG_PA11: CN1.6 U8.5 | length 735.3
  Top Layer w8: CN1.6@986.85,458.74 986.85,544.85 1325.63,883.63 U8.5@1325.63,1053.74
MG_PA12: CN1.7 U8.6 | length 841.9
  Top Layer w8: CN1.7@1086.85,358.74 1036.85,408.74 1036.85,564.85 1341.38,869.38 U8.6@1341.38,1053.74
MG_PA13: CN1.8 U8.7 | length 707
  Top Layer w8: CN1.8@1086.85,458.74 1086.85,586.22 1357.13,856.5 U8.7@1357.13,1053.74
MG_PA14: CN1.9 U8.8 | length 813.5
  Top Layer w8: CN1.9@1186.85,358.74 1136.85,408.74 1136.85,604.85 1372.87,840.87 U8.8@1372.87,1053.74
MG_PA15: CN1.10 U8.9 | length 678.6
  Top Layer w8: CN1.10@1186.85,458.74 1186.85,624.85 1388.62,826.62 U8.9@1388.62,1053.74
MG_PB0: CN1.11 R48.1 U8.10 | length 1998
  Top Layer w8: 1236.85,644.85 1404.37,812.37 U8.10@1404.37,1053.74
  Top Layer w10: 1236.85,644.85 1236.85,408.74 CN1.11@1286.85,358.74
  Bottom Layer w12: CN1.11@1268.71,361.29 1279.06,350.94 1448.5,181.5 2349.93,181.5 R48.1@2376.22,207.8 ; CN1.11@1286.85,358.74 CN1.11@1306.85,358.74
MG_PB1: CN1.12 R52.1 U8.11 | length 2028.9
  Top Layer w8: CN1.12@1286.85,458.74 1286.85,664.85 1420.12,798.12 U8.11@1420.12,1053.74
  Bottom Layer w12: CN1.12@1286.85,458.74 1236.85,408.74 1236.85,333.74 1419.09,151.5 2332.51,151.5 R52.1@2376.22,107.8
MG_PB2: CN1.13 R49.2 U8.12 | length 2511.6
  Top Layer w8: CN1.13@1376.22,352.8 1336.85,392.17 1336.85,684.85 1435.87,783.87 U8.12@1435.87,1053.74
  Bottom Layer w12: CN1.13@1386.85,333.74 CN1.13@1386.85,358.74 1386.85,303.15 1478.5,211.5 2229.93,211.5 2316.22,297.8 2716.22,297.8 2786.22,227.8 2886.22,227.8 2931.22,272.8 R49.2@2936.22,277.8
MG_PB3: CN1.14 R50.2 U8.13 | length 2372.6
  Top Layer w8: CN1.14@1386.85,458.74 1386.85,704.85 1451.61,769.61 U8.13@1451.61,1053.74
  Bottom Layer w12: CN1.14@1386.85,458.74 1436.85,408.74 1436.85,313.15 1507.2,242.8 2221.22,242.8 2306.22,327.8 2886.22,327.8 2931.22,372.8 R50.2@2936.22,377.8
MG_PB4: CN1.27 U8.18 | length 1136.7
  Top Layer w8: U8.18@1530.35,1053.74 1530.35,699.65 1657.62,572.38 2018.21,572.38 2036.85,553.74 2036.85,408.74 CN1.27@2086.85,358.74
MG_PB5: CN1.28 U8.19 | length 1039
  Top Layer w8: U8.19@1546.1,1053.74 1546.1,713.9 1666.41,593.59 2042,593.59 2086.85,548.74 CN1.28@2086.85,458.74
MG_PB6: CN1.29 U8.20 | length 1179.8
  Top Layer w8: U8.20@1561.85,1053.74 1561.85,728.15 1675.19,614.81 2060.78,614.81 2136.85,538.74 2136.85,408.74 CN1.29@2186.85,358.74
MG_PB7: CN1.32 U8.21 | length 1157.5
  Top Layer w8: U8.21@1648.46,1140.35 1665.24,1140.35 1671.85,1133.74 1671.85,937.17 1705.91,903.11 1705.91,724.68 1756.85,673.74 2371.85,673.74 CN1.32@2386.85,658.74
